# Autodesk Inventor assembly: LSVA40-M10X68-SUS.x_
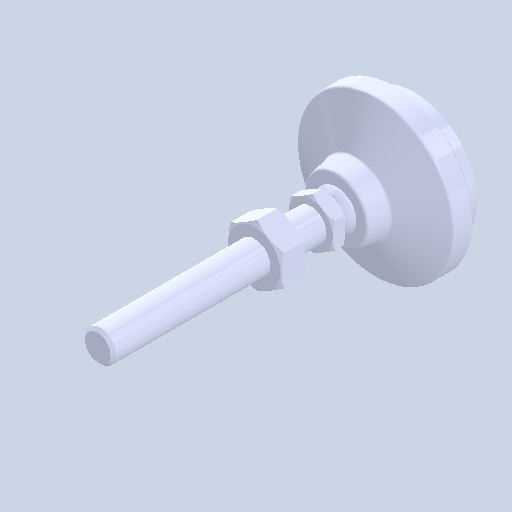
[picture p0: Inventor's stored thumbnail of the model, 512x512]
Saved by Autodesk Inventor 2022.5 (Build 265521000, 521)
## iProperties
Created: 2024-08
Part Number: LSVA40-M10X68-SUS.x_
Document SubType Name: Assembly
Designer: ImaoCorp
Author: ImaoCorp
Sending System: SOLIDWORKS 2022-2022290
MC: AMD64
MC_MODEL: Intel64 Family 6 Model 60 Stepping 3, GenuineIntel
OS: Windows_NT
FRU: Parasolid Version 33.1, build 260,  4-25-2022
FORMAT: text
GUISE: transmit
KEY: FILELSVA40-M10X68-SUS.x_t
DATE: Fri Aug 23 16:07:18 2024
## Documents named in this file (4)
- X:\14_SW2022-Inv2022\06_2024-10新製品(SME)\ELS_データ\l\lsva40-m10x68-sus\LSVA40-M10X68-SUS.x_.iam
- X:\14_SW2022-Inv2022\06_2024-10新製品(SME)\ELS_データ\l\lsva40-m10x68-sus\LSVA40-M10X68-SUS_01.ipt
- X:\14_SW2022-Inv2022\06_2024-10新製品(SME)\ELS_データ\l\lsva40-m10x68-sus\LSVA40-M10X68-SUS_02.ipt
- X:\14_SW2022-Inv2022\06_2024-10新製品(SME)\ELS_データ\l\lsva40-m10x68-sus\LSVA40-M10X68-SUS_03.ipt
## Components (3 placed, 3 different names)
1. LSVA40-M10X68-SUS_01
2. LSVA40-M10X68-SUS_02
3. LSVA40-M10X68-SUS_03
